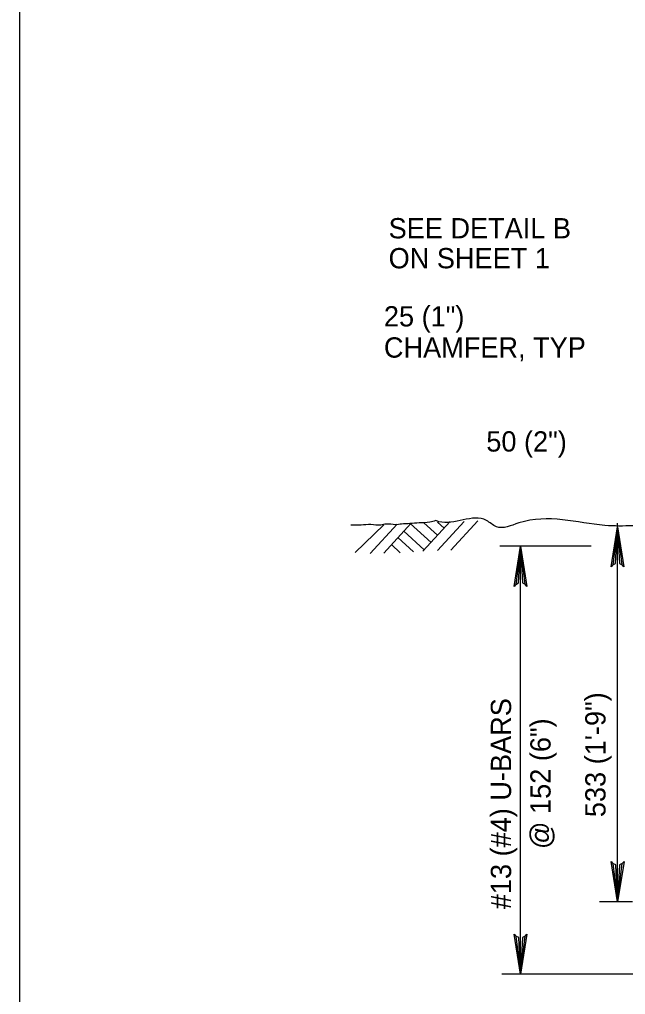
# Model space of a CAD drawing. Extents: x 638455 to 640199, y 298558 to 299152.
# Drawn here: x 639333.6 to 639434, y 298695 to 298856.5 of the extents above; entities that cross this region are included whole.
import ezdxf

# ---------------------------------------------------------------- set-up
doc = ezdxf.new("R2010")
doc.units = 0
for name, color, linetype in [('1', 7, 'Continuous'), ('2', 7, 'Continuous'), ('3', 7, 'Continuous')]:
    doc.layers.add(name, color=color, linetype=linetype)

msp = doc.modelspace()

# ---------------------------------------------------------------- linework, layer by layer
at = {"layer": '1'}
msp.add_lwpolyline([(640119.61, 298573.25), (640119.61, 299137.25), (639333.61, 299137.25), (639333.61, 298573.25), (640119.61, 298573.25), (640119.61, 298599.61), (639919.61, 298599.61), (639919.61, 298664.29), (640119.61, 298664.29), (640119.61, 298693.25), (639919.61, 298693.25), (639919.61, 298573.25), (639998.42, 298573.25), (639998.42, 298599.61), (639998.42, 298573.25), (640075.42, 298573.25), (640075.42, 298599.61), (640075.42, 298587.29), (640119.61, 298587.29)], dxfattribs=at)
at = {"layer": '2'}
for p, q in [((639400.45, 298768.43), (639404.95, 298773.35)), ((639400.59, 298773.13), (639402.84, 298771.07)), ((639402.83, 298768.53), (639407.26, 298773.37)), ((639402.87, 298773.23), (639403.94, 298772.25)), ((639405.08, 298768.63), (639409.51, 298773.47)), ((639432.68, 298710.38), (639432.68, 298773.08)), ((639389.23, 298768.2), (639393.97, 298772.79)), ((639391.7, 298768.04), (639396.18, 298772.93)), ((639393.95, 298768.14), (639398.43, 298773.03)), ((639397.26, 298771.75), (639400.64, 298768.66)), ((639398.33, 298773.03), (639401.79, 298769.87)), ((639396.3, 298770.7), (639398.87, 298768.35)), ((639395.22, 298769.53), (639396.69, 298768.18)), ((639428.3, 298769.27), (639413.17, 298769.27)), ((639416.61, 298698.37), (639416.61, 298769.27)), ((639435.18, 298710.38), (639429.68, 298710.38)), ((639456.25, 298698.37), (639413.51, 298698.37))]:
    msp.add_line(p, q, dxfattribs=at)
for points in [[(639431.88, 298766.16), (639432.34, 298766.4), (639432.68, 298772.49), (639431.88, 298766.16), (639431.6, 298765.84), (639432.68, 298772.49), (639432.98, 298766.4), (639433.43, 298766.18), (639432.68, 298772.49), (639433.73, 298765.84), (639433.43, 298766.18)], [(639415.81, 298762.94), (639416.27, 298763.18), (639416.61, 298769.27), (639415.81, 298762.94), (639415.54, 298762.61), (639416.61, 298769.27), (639416.91, 298763.18), (639417.36, 298762.96), (639416.61, 298769.27), (639417.67, 298762.61), (639417.36, 298762.96)], [(639433.47, 298716.71), (639433.01, 298716.47), (639432.68, 298710.38), (639433.47, 298716.71), (639433.75, 298717.03), (639432.68, 298710.38), (639432.38, 298716.47), (639431.92, 298716.69), (639432.68, 298710.38), (639431.62, 298717.03), (639431.92, 298716.69)], [(639417.4, 298704.7), (639416.95, 298704.47), (639416.61, 298698.37), (639417.4, 298704.7), (639417.68, 298705.03), (639416.61, 298698.37), (639416.31, 298704.46), (639415.85, 298704.69), (639416.61, 298698.37), (639415.55, 298705.03), (639415.85, 298704.69)]]:
    msp.add_lwpolyline(points, dxfattribs=at)
msp.add_spline([(639455, 298773.11), (639451.9, 298773.11), (639449.41, 298773.53), (639439.9, 298773.11), (639430.6, 298772.7), (639416.33, 298773.11), (639412.61, 298772.49), (639410.96, 298773.53), (639403.1, 298773.32), (639402.56, 298773.5)], degree=3, dxfattribs=at)
at = {"layer": '3'}
msp.add_spline([(639402.56, 298773.5), (639401.6, 298773.24), (639399.84, 298773.12), (639398.28, 298773), (639396.9, 298772.93), (639395.89, 298772.81), (639394.33, 298772.93), (639393.45, 298772.75), (639391.82, 298772.87), (639390.19, 298772.75), (639389.12, 298772.75), (639388.5, 298772.75)], degree=3, dxfattribs=at)

# ---------------------------------------------------------------- texts
for s, p in [('SEE DETAIL B', (639394.76, 298820.25)), ('ON SHEET 1', (639394.76, 298815.29)), ('25 (1")', (639393.98, 298805.66)), ('CHAMFER, TYP', (639393.98, 298800.5)), ('50 (2")', (639410.94, 298784.94))]:
    msp.add_text(s, height=3.36, dxfattribs=at).set_placement(p)
for s, p in [('533 (1\'-9")', (639430.69, 298724.39)), ('#13 (#4) U-BARS', (639415.05, 298709.14)), ('@ 152 (6")', (639421.59, 298719.11))]:
    msp.add_text(s, height=3.36, rotation=90, dxfattribs=at).set_placement(p)

doc.saveas('drawing.dxf')
